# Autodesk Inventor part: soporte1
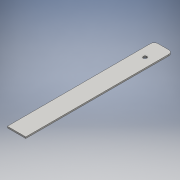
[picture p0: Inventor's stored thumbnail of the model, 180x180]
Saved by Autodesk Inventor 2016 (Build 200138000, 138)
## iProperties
Created: 2016-06
Part Number: soporte1
Material: Genérico
Document SubType Name: Modeling
Designer: adm
Density: 1 g/cm^3
Appearance: Valor por defecto
Author: adm
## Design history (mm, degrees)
sketch "Boceto1"
  geometry: L1 (-25, -200)-(25, -200); L2 (25, -200)-(25, 200); L3 (25, 200)-(-25, 200); L4 (-25, 200)-(-25, -200); L5 (-25, -200)-(25, 200); L6 (25, -200)-(-25, 200); C1 r 5 at (0, 150); 2 further points
  constraints: 12 end point, 2 midpoint, 2 parallel, 1 centre point, 1 coincident, 1 horizontal, 1 perpendicular
  dimensions: "d0" = 50 distance of L3.end L2.end; "d1" = 400 distance of L2.end L1.end; "d2" = 50 distance from line of point (0, 150) L3; "d3" = 10 diameter of C1
extrude "Extrusión1" new body sketch "Boceto1" distance "d4" = 4; taper "d5" = 0 deg
fillet "Empalme1" dims "d6" = 10
node "Sólido1"
